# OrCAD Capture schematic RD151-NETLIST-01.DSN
size A3
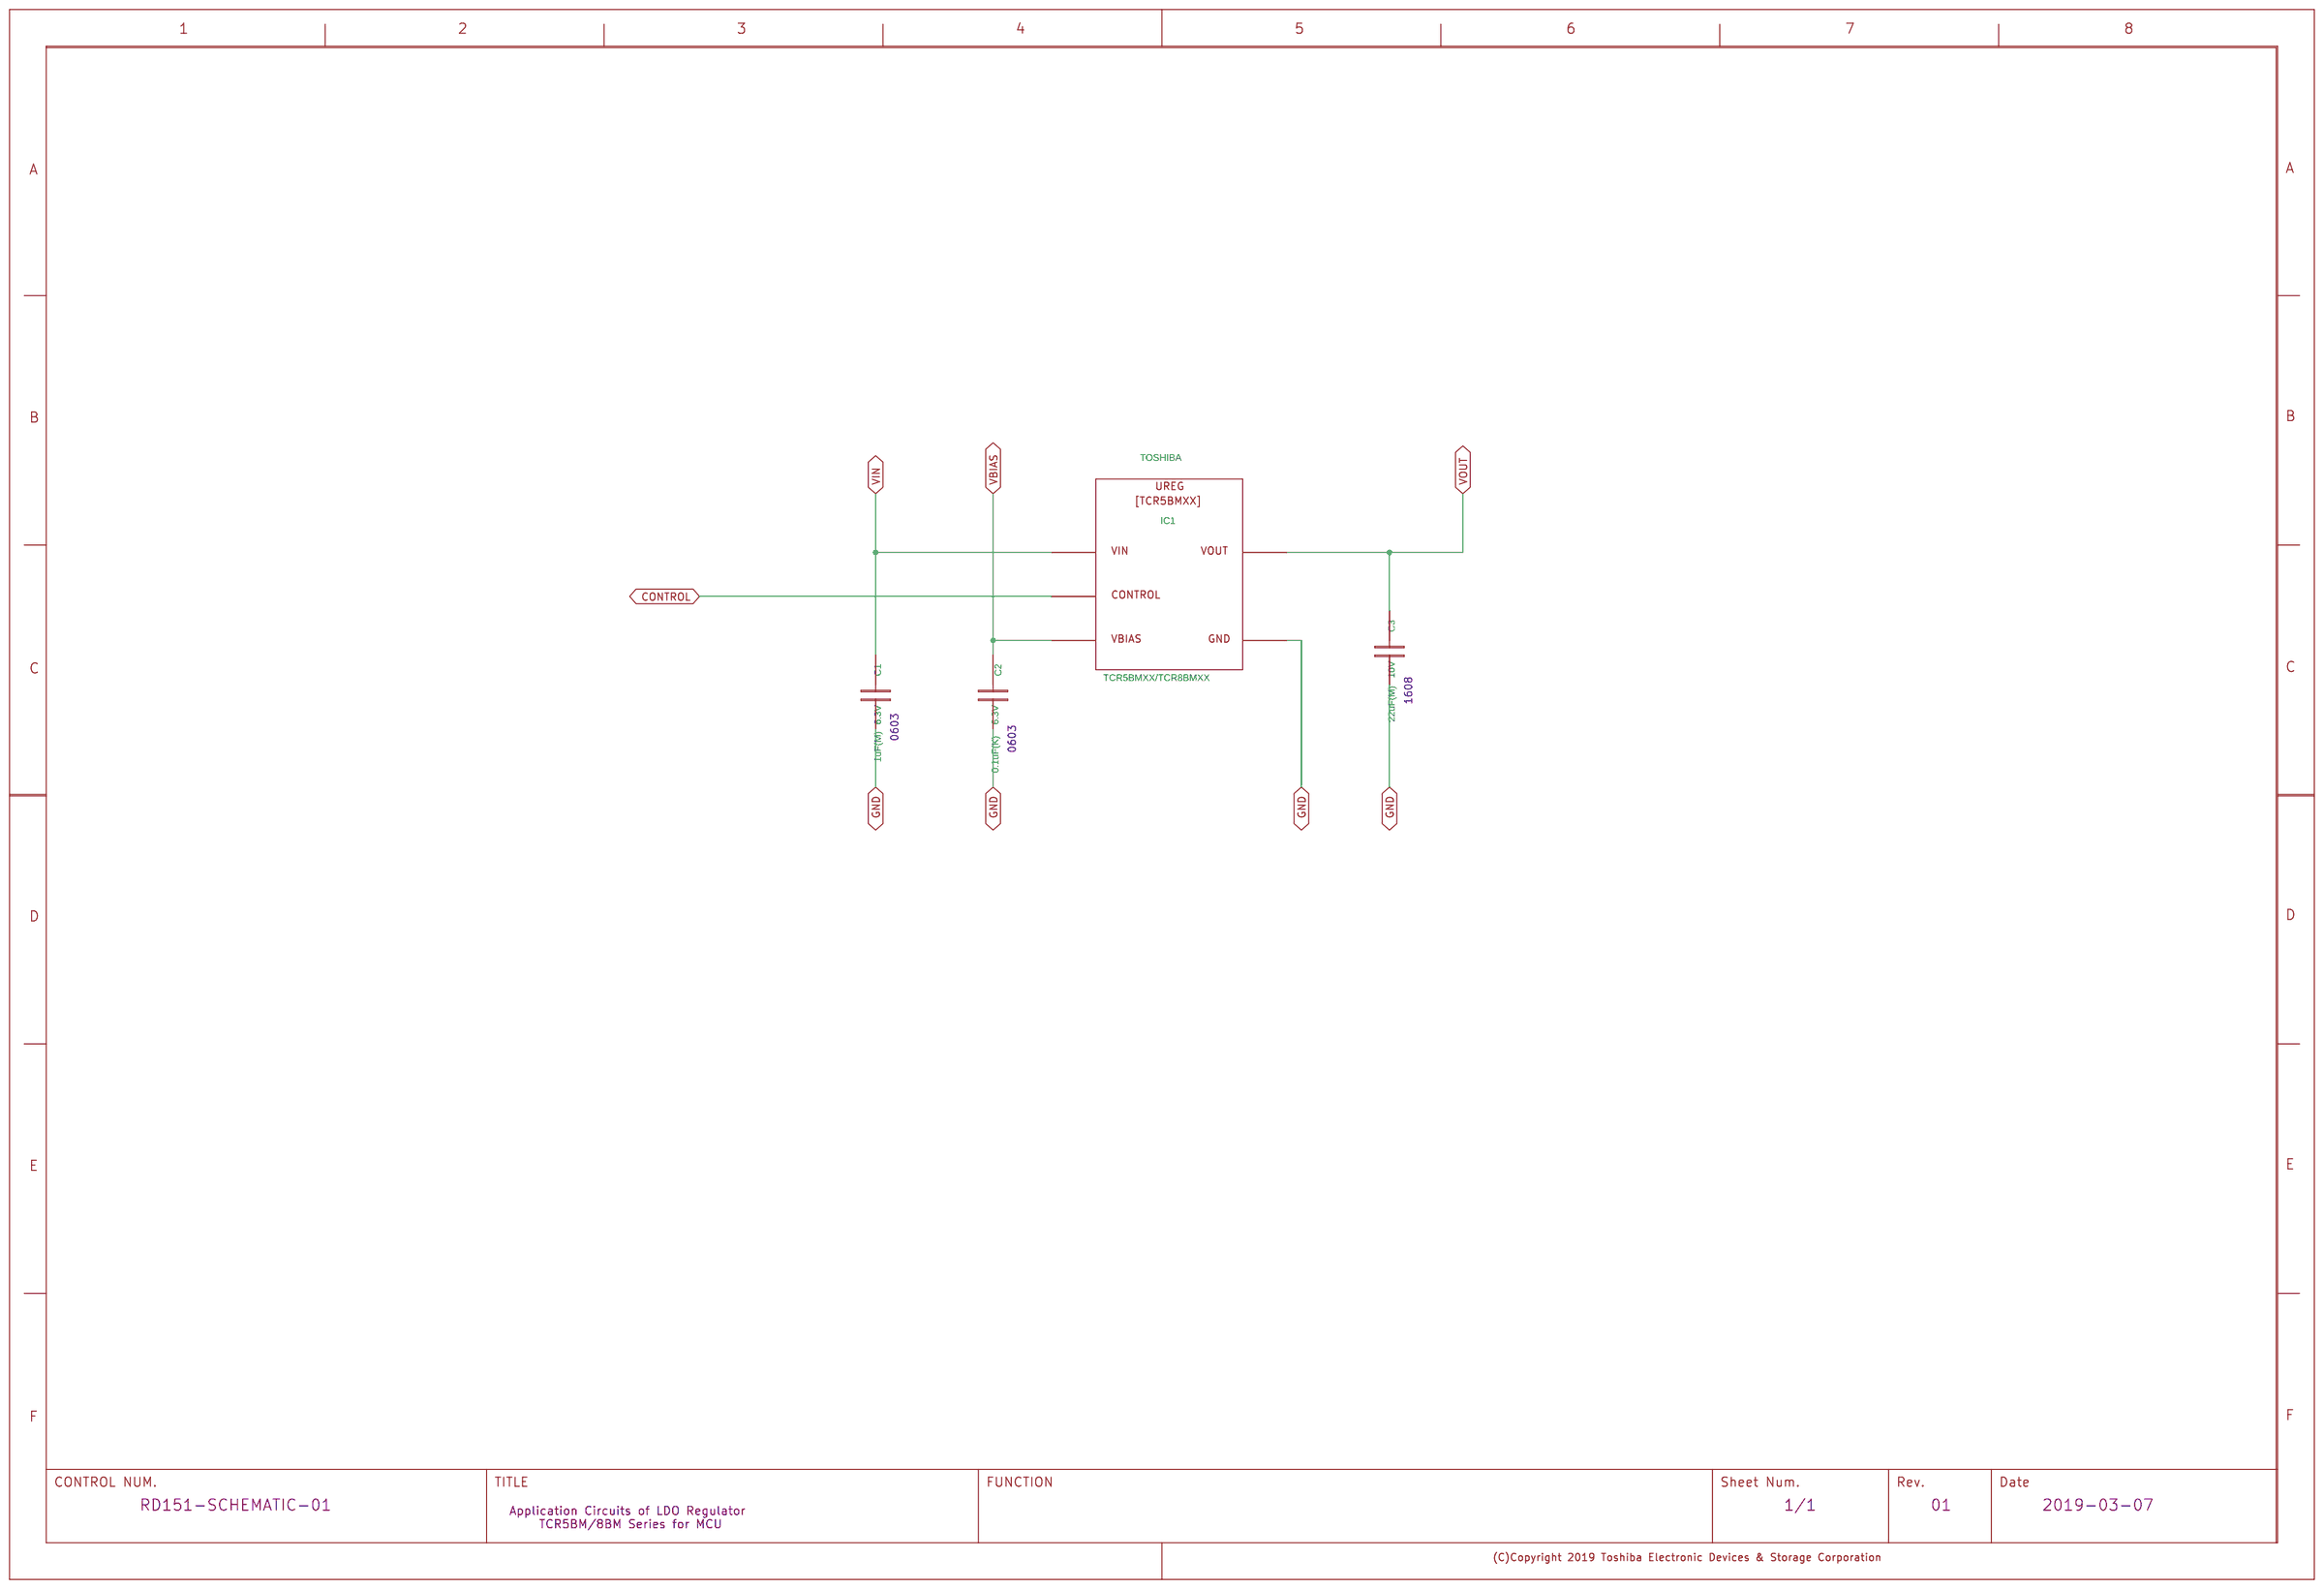
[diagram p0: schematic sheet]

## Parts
C1  C
C2  C
C3  C
IC1  TCR5BM
U?#1  WAKU_DEF100_2019

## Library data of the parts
C1 = C: COMP: PRT_2; COMPONENTTYPE: 4; VAL1: 1uF(M); VAL2: 6.3V; VAL3: GRM033R60J105ME11#
C2 = C: COMP: PRT_3; COMPONENTTYPE: 4; VAL1: 0.1uF(K); VAL2: 6.3V; VAL3: GRM033R60J104KE19#
C3 = C: COMP: PRT_4; COMPONENTTYPE: 4; VAL1: 22uF(M); VAL2: 10V; VAL3: GRM188R61A226ME15#
IC1 = TCR5BM: COMP: PRT_1; COMPONENTTYPE: 4; USERCOMPTEXT3: TOSHIBA; VAL3: TCR5BMXX/TCR8BMXX
U?#1 = WAKU_DEF100_2019: COMPONENTTYPE: 2; DATE: 2019-03-07; DRAWINGNUMBER: RD151-SCHEMATIC-01; REVISION: 01; SHEETNUMBER: 1/1; TITLE: Application Circuits of LDO Regulator / TCR5BM/8BM Series for MCU; UPDATEDATE: 2019/03/12; UPDATETIME: 18:13:48

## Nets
GND: C1.1 C2.1 C3.1 IC1.5
VIN: C1.2 IC1.4
CONTROL: IC1.3
VBIAS: C2.2 IC1.2
VOUT: C3.2 IC1.1

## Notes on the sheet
- 1608
- 0603
- 0603
